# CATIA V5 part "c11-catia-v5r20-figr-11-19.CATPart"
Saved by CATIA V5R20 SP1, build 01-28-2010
Part number: Part1
Bounding box of the stored display mesh (mm): x -89.703 to 75.958, y -127.286 to 108.862, z -26.487 to 19.815
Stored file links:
  D:\v5_r20\psrt_files_downloaded\c11\c11-catia-v5r20-figr-11-19.CATPart
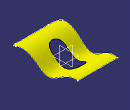
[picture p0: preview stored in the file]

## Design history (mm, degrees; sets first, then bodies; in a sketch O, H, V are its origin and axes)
Set1
  Extrude1: Element1 Sketch3, Lim1 86, Lim2 94, Direction yz-plane
  Sketch1 on xy-plane, origin (0, 0, 0), H (1, 0, 0), V (0, 1, 0)
    line L1 (64.3059, 108.8616) -> (75.9293, -106.0218)
    arc A1 centre (55.7837, -107.1115) radius 20.175 from (75.9293, -106.0218) to (55.7837, -127.2865) cw
    line L2 (55.7837, -127.2865) -> (-64.7868, -127.2865)
    arc A2 centre (-64.7868, -102.3613) radius 24.9252 from (-64.7868, -127.2865) to (-89.6873, -101.2501) cw
    line L3 (-89.6873, -101.2501) -> (-80.3115, 108.8616)
    line L4 (-80.3115, 108.8616) -> (64.3059, 108.8616)
    tangency: A1 L1, A2 L2, A2 L3, A1 L2
    horizontal: L2 H, L4 H
  Extrude2: Element1 Sketch1, Lim1 86, Lim2 94, Direction xy-plane
  Split1: ToCut Extrude1, Cutting Extrude2
  Sketch2 on xy-plane, origin (0, 0, 0), H (1, 0, 0), V (0, 1, 0)
    construction line L1 (-11.3849, 28.4134) -> (-11.3849, -36.9379)
    line L2 (12.8382, 28.4134) -> (12.8382, -36.9379)
    line L3 (-35.608, -36.9379) -> (-35.608, 28.4134)
    arc A1 centre (-11.3849, -36.9379) radius 24.2231 from (12.8382, -36.9379) to (-35.608, -36.9379) cw
    arc A2 centre (-11.3849, 28.4134) radius 24.2231 from (-35.608, 28.4134) to (12.8382, 28.4134) cw
    vertical: L1 V
    tangency: A1 L2, A2 L2, A1 L3, A2 L3
    parallelism: L1 L2
  Extrude3: Element1 Sketch2, Lim1 86, Lim2 94, Direction xy-plane
  Split2: ToCut Split1, Cutting Extrude3
  Boundary1: Boundary edge of Split2, Support Split2
Body1 (main body)
  Sketch3 on yz-plane, origin (0, 0, 0), H (0, 1, 0), V (0, 0, 1)
    spline S1 through (-130.9721, 0) (-85.5087, 19.8151) (-38.0512, 0) (0, -25.6483) (60.0541, -1.7202) (134.7951, -4.3868)
    point P1 (-130.9721, 0)
    point P2 (-38.0512, 0)
    point P3 (0, -25.6483)
    coincidence: P1 H, P2 H, P3 V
